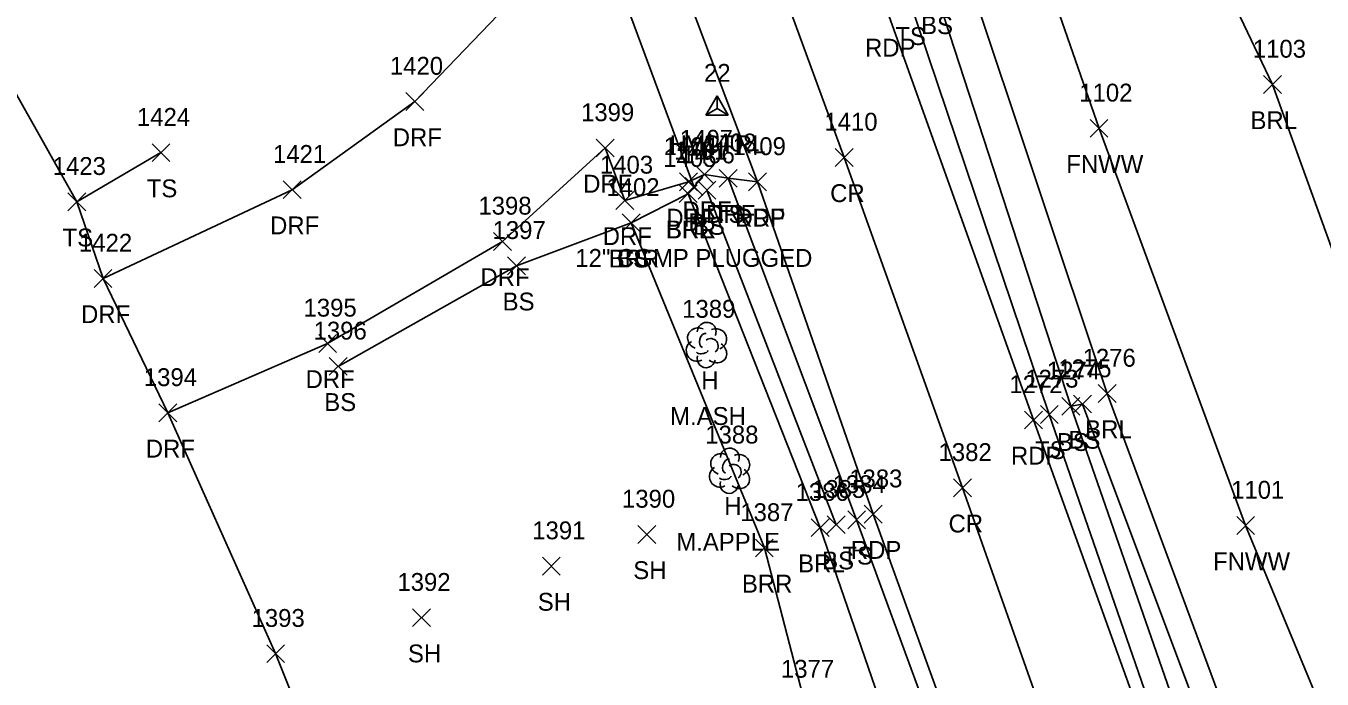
# Model space of a CAD drawing. Extents: x 1443590 to 1445966, y 578314 to 580556.
# Drawn here: x 1445262.8 to 1445407.8, y 578494.4 to 578567.5 of the extents above; entities that cross this region are included whole.
import ezdxf

# ---------------------------------------------------------------- set-up
doc = ezdxf.new("R2010")
doc.units = 0
for name, color, linetype in [('C_A', 7, 'Continuous'), ('C_I', 7, 'Continuous'), ('CPSM', 7, 'Continuous'), ('D_A', 7, 'Continuous'), ('D_C', 7, 'Continuous'), ('D_I', 7, 'Continuous'), ('D_TIC', 7, 'Continuous'), ('DCP', 7, 'Continuous'), ('L_A', 7, 'Continuous'), ('L_C', 7, 'Continuous'), ('L_I', 7, 'Continuous'), ('L_TIC', 7, 'Continuous'), ('LABL', 7, 'Continuous'), ('LELB', 7, 'Continuous'), ('LFNC', 7, 'Continuous'), ('LSOGP', 7, 'Continuous'), ('LTD', 7, 'Continuous'), ('P_A', 7, 'Continuous'), ('P_I', 7, 'Continuous'), ('P_TIC', 7, 'Continuous'), ('PET', 7, 'Continuous'), ('PRC', 7, 'Continuous'), ('R_A', 7, 'Continuous'), ('R_I', 7, 'Continuous'), ('R_TIC', 7, 'Continuous'), ('RDF', 7, 'Continuous')]:
    doc.layers.add(name, color=color, linetype=linetype)

msp = doc.modelspace()

# ---------------------------------------------------------------- linework, layer by layer
at = {"layer": 'CPSM'}
for p, q in [((1445338.84, 578557.52), (1445340.09, 578559.68)), ((1445341.34, 578557.52), (1445340.09, 578559.68)), ((1445340.09, 578558.24), (1445340.09, 578559.68)), ((1445338.84, 578557.52), (1445340.09, 578558.24)), ((1445338.84, 578557.52), (1445341.34, 578557.52)), ((1445340.09, 578558.24), (1445340.09, 578558.24)), ((1445340.09, 578558.24), (1445341.34, 578557.52))]:
    msp.add_line(p, q, dxfattribs=at)
at = {"layer": 'D_TIC'}
for points in [[(1445336.51, 578548.52), (1445338.51, 578550.52)], [(1445338.51, 578548.52), (1445336.51, 578550.52)]]:
    msp.add_lwpolyline(points, dxfattribs=at)
at = {"layer": 'DCP'}
msp.add_lwpolyline([(1445325.76, 578581.28), (1445337.51, 578549.52)], dxfattribs=at)
at = {"layer": 'L_TIC'}
for points in [[(1445401.21, 578559.94), (1445403.21, 578561.94)], [(1445403.21, 578559.94), (1445401.21, 578561.94)], [(1445381.81, 578555.03), (1445383.81, 578557.03)], [(1445383.81, 578555.03), (1445381.81, 578557.03)], [(1445276.9, 578552.31), (1445278.9, 578554.31)], [(1445278.9, 578552.31), (1445276.9, 578554.31)], [(1445340.33, 578549.44), (1445342.33, 578551.44)], [(1445342.33, 578549.44), (1445340.33, 578551.44)], [(1445337.96, 578548.11), (1445339.96, 578550.11)], [(1445339.96, 578548.11), (1445337.96, 578550.11)], [(1445267.48, 578546.81), (1445269.48, 578548.81)], [(1445269.48, 578546.81), (1445267.48, 578548.81)], [(1445335.85, 578547.71), (1445337.85, 578549.71)], [(1445337.85, 578547.71), (1445335.85, 578549.71)], [(1445335.85, 578547.71), (1445337.85, 578549.71)], [(1445337.85, 578547.71), (1445335.85, 578549.71)], [(1445329.48, 578544.45), (1445331.48, 578546.45)], [(1445331.48, 578544.45), (1445329.48, 578546.45)], [(1445329.48, 578544.45), (1445331.48, 578546.45)], [(1445331.48, 578544.45), (1445329.48, 578546.45)], [(1445316.67, 578539.64), (1445318.67, 578541.64)], [(1445318.67, 578539.64), (1445316.67, 578541.64)], [(1445296.72, 578528.38), (1445298.72, 578530.38)], [(1445298.72, 578528.38), (1445296.72, 578530.38)], [(1445382.72, 578525.34), (1445384.72, 578527.34)], [(1445384.72, 578525.34), (1445382.72, 578527.34)], [(1445378.66, 578523.91), (1445380.66, 578525.91)], [(1445380.66, 578523.91), (1445378.66, 578525.91)], [(1445378.66, 578523.91), (1445380.66, 578525.91)], [(1445380.66, 578523.91), (1445378.66, 578525.91)], [(1445379.95, 578524.16), (1445381.95, 578526.16)], [(1445381.95, 578524.16), (1445379.95, 578526.16)], [(1445376.25, 578523), (1445378.25, 578525)], [(1445378.25, 578523), (1445376.25, 578525)], [(1445350.62, 578510.32), (1445352.62, 578512.32)], [(1445352.62, 578510.32), (1445350.62, 578512.32)], [(1445352.41, 578510.65), (1445354.41, 578512.65)], [(1445354.41, 578510.65), (1445352.41, 578512.65)], [(1445354.7, 578511.19), (1445356.7, 578513.19)], [(1445356.7, 578511.19), (1445354.7, 578513.19)], [(1445398.21, 578510.56), (1445400.21, 578512.56)], [(1445400.21, 578510.56), (1445398.21, 578512.56)], [(1445331.24, 578509.56), (1445333.24, 578511.56)], [(1445333.24, 578509.56), (1445331.24, 578511.56)], [(1445344.38, 578508.05), (1445346.38, 578510.05)], [(1445346.38, 578508.05), (1445344.38, 578510.05)], [(1445320.55, 578506.02), (1445322.55, 578508.02)], [(1445322.55, 578506.02), (1445320.55, 578508.02)], [(1445306.03, 578500.24), (1445308.03, 578502.24)], [(1445308.03, 578500.24), (1445306.03, 578502.24)], [(1445289.72, 578496.21), (1445291.72, 578498.21)], [(1445291.72, 578496.21), (1445289.72, 578498.21)]]:
    msp.add_lwpolyline(points, dxfattribs=at)
at = {"layer": 'LABL'}
for points in [[(1445467.84, 578360.06), (1445455.38, 578392.07), (1445446.82, 578428.87), (1445442.38, 578441.48), (1445436.55, 578457.59), (1445425.34, 578488.87), (1445418.21, 578516.65), (1445402.21, 578560.94), (1445385.83, 578595.27), (1445371.99, 578640.68), (1445356.66, 578684.35), (1445342.86, 578722.22), (1445331.82, 578758.2), (1445312.95, 578811.34), (1445309.58, 578818.49), (1445306.72, 578822.66), (1445303.45, 578826.18), (1445294.95, 578830.16), (1445285.99, 578855.57), (1445278.07, 578895.34), (1445273.01, 578922.07), (1445267.74, 578942.65), (1445247.28, 578957.13)], [(1445292.63, 578789.9), (1445288, 578780.72), (1445303.45, 578740.92), (1445320.45, 578696.23), (1445336.45, 578651.8), (1445353.16, 578609.77), (1445368.17, 578573), (1445383.72, 578526.34), (1445398.46, 578486.57), (1445412.31, 578451.09), (1445415.12, 578445.83), (1445420.11, 578428.88), (1445425.31, 578411.87), (1445435.24, 578381.31), (1445438.11, 578382.76), (1445447.54, 578352.71)], [(1445345.27, 578443.57), (1445353.95, 578463.43), (1445352.32, 578466.56), (1445349.93, 578491.52), (1445345.38, 578509.05), (1445330.48, 578545.45), (1445336.85, 578548.71)], [(1445414.81, 578340.8), (1445401.7, 578375.55), (1445388.17, 578412.4), (1445382.57, 578425.95), (1445377.8, 578432.04), (1445377.55, 578433.04), (1445376.34, 578435.51), (1445372.5, 578441.21), (1445366.97, 578466.65), (1445351.62, 578511.32), (1445336.85, 578548.71)]]:
    msp.add_lwpolyline(points, dxfattribs=at)
at = {"layer": 'LELB'}
for points in [[(1445222.69, 578937.93), (1445234.28, 578911.39), (1445254.78, 578861.13), (1445268.94, 578819.8), (1445281.41, 578785.26), (1445283.41, 578779.74), (1445299.6, 578739.58), (1445316.15, 578694.47), (1445332.79, 578650.27), (1445347.4, 578607.95), (1445361.62, 578570.36), (1445377.25, 578524), (1445391.22, 578483.59), (1445406.36, 578442.9), (1445418.34, 578410.04), (1445429.91, 578378.9), (1445440.4, 578350.18)], [(1445336.45, 578651.8), (1445350.45, 578608.68), (1445364.47, 578571.58), (1445379.66, 578524.91), (1445393.71, 578484.47), (1445409.17, 578449.94), (1445411.12, 578445.67), (1445411.54, 578444.09), (1445413.6, 578439.47), (1445415.72, 578428.29), (1445422.38, 578411.18), (1445431.91, 578379.51), (1445442.14, 578350.66)], [(1445268.48, 578547.81), (1445277.9, 578553.31)], [(1445416.98, 578341.83), (1445404.21, 578376.42), (1445390.71, 578413.34), (1445383.61, 578436.1), (1445371.7, 578468.44), (1445355.7, 578512.19), (1445341.33, 578550.44)], [(1445353.41, 578511.65), (1445338.96, 578549.11)], [(1445297.72, 578529.38), (1445317.67, 578540.64), (1445330.48, 578545.45)], [(1445379.66, 578524.91), (1445380.95, 578525.16), (1445395.89, 578485.33), (1445412.31, 578451.09)]]:
    msp.add_lwpolyline(points, dxfattribs=at)
at = {"layer": 'LFNC'}
msp.add_lwpolyline([(1445459.96, 578349.35), (1445445.8, 578387.44), (1445435.66, 578413.46), (1445430.43, 578428.44), (1445420.82, 578457.49), (1445411.95, 578480.76), (1445399.21, 578511.56), (1445382.81, 578556.03), (1445370.45, 578591.65), (1445354.37, 578635.55), (1445339.12, 578673.28), (1445323.48, 578719.9), (1445315.49, 578748.71)], dxfattribs=at)
at = {"layer": 'LSOGP'}
msp.add_lwpolyline([(1445251.74, 578577.57), (1445268.47, 578547.81), (1445271.43, 578539.23), (1445278.67, 578524.17), (1445290.72, 578497.22), (1445299.63, 578474.91), (1445308.71, 578448.35), (1445314.45, 578432.69), (1445323.21, 578416.31), (1445333.13, 578404.92), (1445332.9, 578402.26), (1445333.6, 578401.15), (1445334.02, 578398.03)], dxfattribs=at)
at = {"layer": 'LTD'}
for p, q in [((1445338.89, 578531.82), (1445338.89, 578531.82)), ((1445338.89, 578531.82), (1445338.89, 578531.82)), ((1445341.46, 578517.74), (1445341.46, 578517.74)), ((1445341.46, 578517.74), (1445341.46, 578517.74))]:
    msp.add_line(p, q, dxfattribs=at)
for centre in [(1445338.93, 578533.26), (1445341.51, 578519.18)]:
    msp.add_arc(centre, 1.05, 335.5272, 180.9563, dxfattribs=at)
for centre, major_axis, ratio, start_param, end_param in [((1445338.09, 578532.49), (1.21, -0.51), 0.895232, 1.570796, 4.712389), ((1445338.68, 578532.28), (-0.208, -0.792), 0.645439, 3.141593, 6.283185), ((1445339.39, 578531.66), (-0.5, 0.667), 0.989748, 3.141593, 6.283185), ((1445339.93, 578532.41), (-1.14, -0.48), 0.949671, 1.570796, 4.712389), ((1445337.8, 578531.12), (0.58, -1.04), 0.959034, 3.141593, 6.283185), ((1445338.43, 578531.07), (-0.625, -0.083), 0.423636, 0, 3.141593), ((1445339.89, 578530.99), (-1.09, 0.79), 0.841452, 1.570796, 4.712389), ((1445338.89, 578530.32), (0.26, 1.06), 0.942809, 1.570796, 4.712389), ((1445340.67, 578518.41), (1.21, -0.51), 0.895232, 1.570796, 4.712389), ((1445342.51, 578518.33), (-1.14, -0.48), 0.949671, 1.570796, 4.712389), ((1445341.26, 578518.2), (-0.208, -0.792), 0.645439, 3.141593, 6.283185), ((1445341.96, 578517.58), (-0.5, 0.667), 0.989748, 3.141593, 6.283185), ((1445340.38, 578517.03), (0.58, -1.04), 0.959034, 3.141593, 6.283185), ((1445341.01, 578516.99), (-0.625, -0.083), 0.423636, 0, 3.141593), ((1445342.46, 578516.91), (-1.09, 0.79), 0.841452, 1.570796, 4.712389), ((1445341.46, 578516.24), (0.26, 1.06), 0.942809, 1.570796, 4.712389)]:
    msp.add_ellipse(centre, major_axis=major_axis, ratio=ratio, start_param=start_param, end_param=end_param, dxfattribs=at)
at = {"layer": 'P_TIC'}
for points in [[(1445353.3, 578551.77), (1445355.3, 578553.77)], [(1445355.3, 578551.77), (1445353.3, 578553.77)], [(1445343.62, 578549.03), (1445345.62, 578551.03)], [(1445345.62, 578549.03), (1445343.62, 578551.03)], [(1445374.47, 578522.38), (1445376.47, 578524.38)], [(1445376.47, 578522.38), (1445374.47, 578524.38)], [(1445366.55, 578514.78), (1445368.55, 578516.78)], [(1445368.55, 578514.78), (1445366.55, 578516.78)], [(1445356.56, 578511.83), (1445358.56, 578513.83)], [(1445358.56, 578511.83), (1445356.56, 578513.83)]]:
    msp.add_lwpolyline(points, dxfattribs=at)
at = {"layer": 'PET'}
for points in [[(1445418.89, 578342.02), (1445405.88, 578377.14), (1445393.26, 578414.23), (1445384.94, 578436.64), (1445373.41, 578468.96), (1445357.56, 578512.83), (1445344.62, 578550.03), (1445330.99, 578586.22), (1445323.64, 578606.66), (1445310.56, 578643.56), (1445297.05, 578680.63), (1445286.07, 578712.45), (1445276.51, 578732.61), (1445268.43, 578753.25), (1445256.91, 578785.04), (1445249.61, 578806.41), (1445230.56, 578857.31), (1445217.97, 578888.99), (1445200.05, 578931.7), (1445199.72, 578935.44), (1445193.89, 578943.66), (1445183.72, 578968.31), (1445171.41, 579000.64)], [(1445204.47, 578977.72), (1445211.07, 578960.69), (1445220.5, 578936.98), (1445230.76, 578910.15), (1445251.08, 578859.52), (1445265.4, 578819.79), (1445279.28, 578781.46), (1445295.62, 578738.27), (1445312.78, 578693.03), (1445329.09, 578649.05), (1445344.77, 578606.81), (1445359.16, 578569.06), (1445375.47, 578523.38), (1445389.92, 578483.27), (1445404.56, 578441.9), (1445416.57, 578409.56), (1445427.35, 578377.72), (1445437.94, 578349.1)]]:
    msp.add_lwpolyline(points, dxfattribs=at)
at = {"layer": 'PRC'}
msp.add_lwpolyline([(1445428.76, 578345.92), (1445416.12, 578381.06), (1445402.82, 578417.2), (1445394.53, 578440.03), (1445382.79, 578472.56), (1445367.55, 578515.78), (1445354.3, 578552.77), (1445340.07, 578591.68), (1445332.93, 578610.75), (1445320.05, 578646.79), (1445306.48, 578683.94), (1445294.78, 578715.83), (1445285.68, 578740.23), (1445278.69, 578759.19), (1445266.72, 578790.29), (1445259.42, 578810.95), (1445240.14, 578861.33), (1445228.56, 578891.21), (1445209.9, 578937.12), (1445195.27, 578973.7), (1445179.73, 579007.4), (1445167.09, 579032.9), (1445157.85, 579050.89), (1445142.74, 579080.19)], dxfattribs=at)
at = {"layer": 'R_TIC'}
for points in [[(1445305.28, 578558.03), (1445307.28, 578560.03)], [(1445307.28, 578558.03), (1445305.28, 578560.03)], [(1445326.58, 578552.83), (1445328.58, 578554.83)], [(1445328.58, 578552.83), (1445326.58, 578554.83)], [(1445337.69, 578549.86), (1445339.69, 578551.86)], [(1445339.69, 578549.86), (1445337.69, 578551.86)], [(1445340.33, 578549.44), (1445342.33, 578551.44)], [(1445342.33, 578549.44), (1445340.33, 578551.44)], [(1445291.56, 578548.16), (1445293.56, 578550.16)], [(1445293.56, 578548.16), (1445291.56, 578550.16)], [(1445335.89, 578549.03), (1445337.89, 578551.03)], [(1445337.89, 578549.03), (1445335.89, 578551.03)], [(1445343.62, 578549.03), (1445345.62, 578551.03)], [(1445345.62, 578549.03), (1445343.62, 578551.03)], [(1445328.77, 578546.96), (1445330.77, 578548.96)], [(1445330.77, 578546.96), (1445328.77, 578548.96)], [(1445315.09, 578542.37), (1445317.09, 578544.37)], [(1445317.09, 578542.37), (1445315.09, 578544.37)], [(1445270.42, 578538.22), (1445272.42, 578540.22)], [(1445272.42, 578538.22), (1445270.42, 578540.22)], [(1445295.54, 578530.95), (1445297.54, 578532.95)], [(1445297.54, 578530.95), (1445295.54, 578532.95)], [(1445277.67, 578523.17), (1445279.67, 578525.17)], [(1445279.67, 578523.17), (1445277.67, 578525.17)]]:
    msp.add_lwpolyline(points, dxfattribs=at)
at = {"layer": 'RDF'}
for points in [[(1445330.99, 578586.22), (1445329.48, 578584.81), (1445327.1, 578580.99), (1445325.1, 578579.69), (1445319.31, 578572.61), (1445306.28, 578559.03), (1445292.56, 578549.16), (1445271.42, 578539.22)], [(1445278.67, 578524.17), (1445296.54, 578531.95), (1445316.09, 578543.37), (1445327.58, 578553.83), (1445329.77, 578547.96), (1445336.89, 578550.03), (1445338.69, 578550.86), (1445341.33, 578550.44), (1445344.62, 578550.03)]]:
    msp.add_lwpolyline(points, dxfattribs=at)

# ---------------------------------------------------------------- texts
at = {"layer": 'C_A'}
msp.add_text('HVCTRL', height=2, dxfattribs=at).set_placement((1445334.79, 578553.24))
at = {"layer": 'C_I'}
msp.add_text('22', height=2, dxfattribs=at).set_placement((1445338.63, 578561.24))
at = {"layer": 'D_A'}
msp.add_text('P', height=2, dxfattribs=at).set_placement((1445336.88, 578544.52))
at = {"layer": 'D_C'}
msp.add_text('12" CGMP PLUGGED', height=2, dxfattribs=at).set_placement((1445324.24, 578540.52))
at = {"layer": 'D_I'}
msp.add_text('1401', height=2, dxfattribs=at).set_placement((1445335.3, 578552.52))
at = {"layer": 'L_A'}
for s, p in [('TS', (1445360.03, 578565.36)), ('BS', (1445362.91, 578566.58)), ('BRL', (1445399.75, 578555.94)), ('FNWW', (1445379.15, 578551.03)), ('TS', (1445276.31, 578548.31)), ('TS', (1445339.74, 578545.44)), ('BRR', (1445334.34, 578543.71)), ('BRL', (1445334.4, 578543.71)), ('BS', (1445337.4, 578544.11)), ('TS', (1445266.89, 578542.81)), ('BRR', (1445327.97, 578540.45)), ('BS', (1445328.92, 578540.45)), ('BS', (1445316.11, 578535.64)), ('H', (1445338.32, 578526.82)), ('BS', (1445296.16, 578524.38)), ('BRL', (1445381.26, 578521.34)), ('TS', (1445375.66, 578519)), ('BS', (1445378.1, 578519.91)), ('BS', (1445378.1, 578519.91)), ('BS', (1445379.39, 578520.16)), ('H', (1445340.9, 578512.74)), ('BRL', (1445349.16, 578506.32)), ('BS', (1445351.85, 578506.65)), ('TS', (1445354.11, 578507.19)), ('FNWW', (1445395.56, 578506.56)), ('SH', (1445330.72, 578505.56)), ('BRR', (1445342.87, 578504.05)), ('SH', (1445320.04, 578502.02)), ('SH', (1445305.52, 578496.24))]:
    msp.add_text(s, height=2, dxfattribs=at).set_placement(p)
at = {"layer": 'L_C'}
for s, p in [('M.ASH', (1445334.84, 578522.82)), ('M.APPLE', (1445335.53, 578508.74))]:
    msp.add_text(s, height=2, dxfattribs=at).set_placement(p)
at = {"layer": 'L_I'}
for s, p in [('1103', (1445400.01, 578563.94)), ('1102', (1445380.6, 578559.03)), ('1424', (1445275.21, 578556.31)), ('1408', (1445338.55, 578553.44)), ('1405', (1445334.08, 578551.71)), ('1405', (1445334.08, 578551.71)), ('1406', (1445336.13, 578552.11)), ('1423', (1445265.79, 578550.81)), ('1402', (1445327.71, 578548.45)), ('1402', (1445327.71, 578548.45)), ('1397', (1445314.98, 578543.64)), ('1389', (1445336.19, 578534.82)), ('1396', (1445294.97, 578532.38)), ('1276', (1445380.97, 578529.34)), ('1274', (1445376.97, 578527.91)), ('1274', (1445376.97, 578527.91)), ('1275', (1445378.25, 578528.16)), ('1273', (1445374.56, 578527)), ('1388', (1445338.77, 578520.74)), ('1385', (1445350.72, 578514.65)), ('1384', (1445353.01, 578515.19)), ('1390', (1445329.46, 578513.56)), ('1386', (1445348.87, 578514.32)), ('1101', (1445397.58, 578514.56)), ('1387', (1445342.69, 578512.05)), ('1391', (1445319.42, 578510.02)), ('1392', (1445304.34, 578504.24)), ('1393', (1445288.03, 578500.21)), ('1377', (1445347.24, 578494.52))]:
    msp.add_text(s, height=2, dxfattribs=at).set_placement(p)
at = {"layer": 'P_A'}
for s, p in [('RDP', (1445356.64, 578564.06)), ('CR', (1445352.74, 578547.77)), ('RDP', (1445342.11, 578545.03)), ('RDP', (1445372.96, 578518.38)), ('CR', (1445365.98, 578510.78)), ('RDP', (1445355.05, 578507.83))]:
    msp.add_text(s, height=2, dxfattribs=at).set_placement(p)
at = {"layer": 'P_I'}
for s, p in [('1410', (1445352.09, 578555.77)), ('1409', (1445341.84, 578553.03)), ('1272', (1445372.78, 578526.38)), ('1382', (1445364.86, 578518.78)), ('1383', (1445354.87, 578515.83))]:
    msp.add_text(s, height=2, dxfattribs=at).set_placement(p)
at = {"layer": 'R_A'}
for p in [(1445303.82, 578554.03), (1445325.12, 578548.83), (1445336.23, 578545.86), (1445338.86, 578545.44), (1445290.1, 578544.16), (1445334.42, 578545.03), (1445342.16, 578545.03), (1445327.3, 578542.96), (1445313.63, 578538.37), (1445268.96, 578534.22), (1445294.07, 578526.95), (1445276.2, 578519.17)]:
    msp.add_text('DRF', height=2, dxfattribs=at).set_placement(p)
at = {"layer": 'R_I'}
for s, p in [('1420', (1445303.5, 578562.03)), ('1399', (1445324.88, 578556.83)), ('1407', (1445335.92, 578553.86)), ('1404', (1445334.12, 578553.03)), ('1408', (1445338.55, 578553.44)), ('1409', (1445341.84, 578553.03)), ('1421', (1445290.43, 578552.16)), ('1403', (1445326.99, 578550.96)), ('1398', (1445313.4, 578546.37)), ('1422', (1445268.73, 578542.22)), ('1395', (1445293.84, 578534.95)), ('1394', (1445275.98, 578527.17))]:
    msp.add_text(s, height=2, dxfattribs=at).set_placement(p)

doc.saveas('drawing.dxf')
